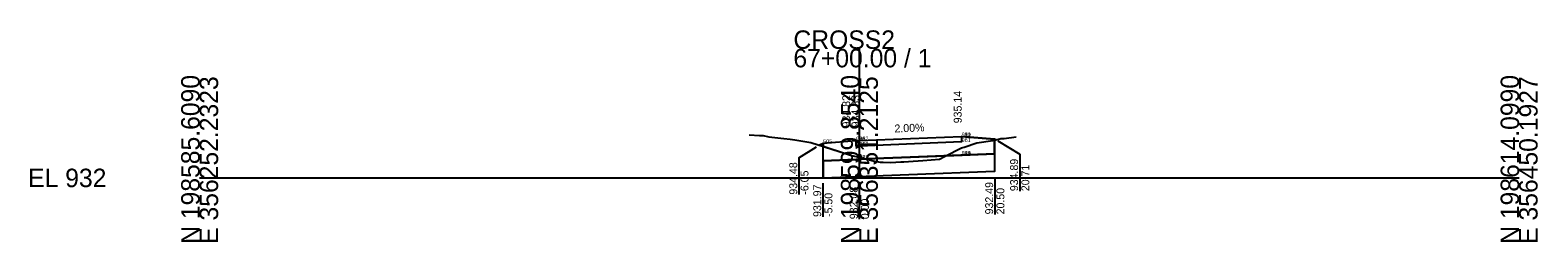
# Model space of a CAD drawing. Extents: x -26 to 203, y -10 to 14021.
# Drawn here: x -25.7 to 202.8, y 7990.3 to 8022.4 of the extents above; entities that cross this region are included whole.
import ezdxf

# ---------------------------------------------------------------- set-up
doc = ezdxf.new("R2010")
doc.units = 0
for name, color, linetype in [('Default', 7, 'Continuous'), ('P_E_XS_Ground', 7, 'Continuous'), ('P_XS', 7, 'Continuous'), ('P_XS_Bold', 7, 'Continuous'), ('P_XS_EAR_CommonGrnd', 7, 'Continuous'), ('P_XS_Lane', 7, 'Continuous'), ('P_XS_Rock', 7, 'Continuous')]:
    doc.layers.add(name, color=color, linetype=linetype)

msp = doc.modelspace()

# ---------------------------------------------------------------- linework, layer by layer
at = {"layer": 'Default'}
for p, q in [((100, 8000), (100, 8019.56)), ((0, 8000), (100, 8000)), ((100, 8000), (200, 8000))]:
    msp.add_line(p, q, dxfattribs=at)
at = {"layer": 'P_E_XS_Ground'}
for p, q in [((83.29, 8006.52), (84.86, 8006.43)), ((84.86, 8006.43), (85.44, 8006.41)), ((85.44, 8006.41), (86.29, 8006.24)), ((86.29, 8006.24), (88.57, 8005.98)), ((88.57, 8005.98), (89.52, 8005.86)), ((89.52, 8005.86), (90.2, 8005.76)), ((90.2, 8005.76), (92.65, 8005.38)), ((117.79, 8005.3), (120.21, 8005.69)), ((120.21, 8005.69), (120.94, 8005.82)), ((120.94, 8005.82), (121.46, 8005.97)), ((121.46, 8005.97), (121.93, 8005.97)), ((121.93, 8005.97), (123.74, 8006.21)), ((92.65, 8005.38), (97.89, 8003.7)), ((97.89, 8003.7), (98.8, 8003.42)), ((98.8, 8003.42), (99.51, 8003.26)), ((99.51, 8003.26), (100, 8003.13)), ((112.16, 8002.86), (112.9, 8003.25)), ((112.9, 8003.25), (115.47, 8004.57)), ((115.47, 8004.57), (115.86, 8004.68)), ((115.86, 8004.68), (117.79, 8005.3)), ((100, 8003.13), (102.1, 8002.61)), ((102.1, 8002.61), (103.13, 8002.4)), ((103.13, 8002.4), (103.59, 8002.39)), ((103.59, 8002.39), (104.79, 8002.34)), ((104.79, 8002.34), (106.28, 8002.43)), ((106.28, 8002.43), (106.76, 8002.43)), ((106.76, 8002.43), (107.45, 8002.48)), ((107.45, 8002.48), (109.62, 8002.63)), ((109.62, 8002.63), (112.16, 8002.86))]:
    msp.add_line(p, q, dxfattribs=at)
at = {"layer": 'P_XS'}
for p, q in [((99.5, 8005.64), (99.5, 8004.81)), ((115.5, 8006.28), (115.5, 8005.45)), ((120.5, 8003.65), (120.5, 8005.88)), ((94.5, 8002.61), (94.5, 8005.24)), ((99.5, 8004.81), (100, 8004.83)), ((115.5, 8005.45), (100, 8004.83)), ((120.5, 8003.65), (100, 8002.83)), ((120.5, 8003.65), (120.5, 8000.98)), ((99.5, 8002.81), (94.5, 8002.61)), ((94.5, 8002.61), (94.5, 7999.94)), ((120.5, 8000.98), (94.5, 7999.94)), ((99.5, 8002.81), (100, 8002.83))]:
    msp.add_line(p, q, dxfattribs=at)
at = {"layer": 'P_XS_EAR_CommonGrnd'}
for points in [[(94.5, 8004.79), (97.89, 8003.7), (98.8, 8003.42), (99.51, 8003.26), (100, 8003.13), (101.04, 8002.87), (113.11, 8003.35), (115.47, 8004.57), (115.86, 8004.68), (117.79, 8005.3), (120.21, 8005.69), (120.5, 8005.74), (120.5, 8005.88), (115.5, 8006.28), (115.5, 8005.45), (100, 8004.83), (99.5, 8004.81), (99.5, 8005.64), (94.5, 8005.24)], [(100, 8005.66), (115.5, 8006.28), (115.5, 8005.45), (100, 8004.83), (99.5, 8004.81), (99.5, 8005.64)], [(120.21, 8005.69), (120.5, 8005.74), (120.5, 8003.65), (113.11, 8003.35), (115.47, 8004.57), (115.86, 8004.68), (117.79, 8005.3)], [(120.5, 8005.74), (120.71, 8005.78), (120.5, 8005.88)], [(93.95, 8004.97), (94.5, 8004.79), (94.5, 8005.24)], [(94.5, 8004.79), (97.89, 8003.7), (98.8, 8003.42), (99.51, 8003.26), (100, 8003.13), (101.04, 8002.87), (100, 8002.83), (99.5, 8002.81), (94.5, 8002.61)], [(107.45, 8002.48), (109.62, 8002.63), (112.16, 8002.86), (112.9, 8003.25), (113.11, 8003.35), (120.5, 8003.65), (120.5, 8000.98), (94.5, 7999.94), (94.5, 8002.61), (99.5, 8002.81), (100, 8002.83), (101.04, 8002.87), (102.1, 8002.61), (103.13, 8002.4), (103.59, 8002.39), (104.79, 8002.34), (106.28, 8002.43), (106.76, 8002.43)], [(107.45, 8002.48), (109.62, 8002.63), (112.16, 8002.86), (112.9, 8003.25), (113.11, 8003.35), (101.04, 8002.87), (102.1, 8002.61), (103.13, 8002.4), (103.59, 8002.39), (104.79, 8002.34), (106.28, 8002.43), (106.76, 8002.43)]]:
    msp.add_lwpolyline(points, close=True, dxfattribs=at)
at = {"layer": 'P_XS_Lane'}
for p, q in [((99.5, 8005.64), (94.5, 8005.24)), ((99.5, 8005.64), (100, 8005.66)), ((100, 8005.66), (115.5, 8006.28)), ((115.5, 8006.28), (120.5, 8005.88)), ((120.5, 8005.88), (120.71, 8005.78)), ((94.5, 8005.24), (93.95, 8004.97))]:
    msp.add_line(p, q, dxfattribs=at)
at = {"layer": 'P_XS_Rock'}
for p, q in [((120.99, 8005.6), (124.3, 8003.58)), ((90.83, 8003.06), (93.49, 8004.69)), ((124.3, 8003.58), (124.3, 7997.99)), ((90.83, 8003.06), (90.83, 7997.46)), ((94.46, 7999.2), (94.46, 7994.08)), ((99.99, 7999.43), (99.99, 7993.74)), ((120.52, 8000.07), (120.52, 7994.47))]:
    msp.add_line(p, q, dxfattribs=at)

# ---------------------------------------------------------------- texts
at = {"layer": 'Default'}
for s, p in [('CROSS2', (90, 8019.56)), ('67+00.00 / 1', (90, 8016.76)), ('EL 932', (-26, 7998.6))]:
    msp.add_text(s, height=2.8, dxfattribs=at).set_placement(p)
for s, p in [('N 198585.6090', (0, 7990)), ('E 356252.2323', (2.8, 7990)), ('N 198599.8540', (100, 7990)), ('E 356351.2125', (102.8, 7990)), ('N 198614.0990', (200, 7990)), ('E 356450.1927', (202.8, 7990))]:
    msp.add_text(s, height=2.8, rotation=90, dxfattribs=at).set_placement(p)
at = {"layer": 'P_XS_Bold'}
for s, p in [('505', (94.5, 8005.24)), ('951', (99.5, 8005.64)), ('9', (99.5, 8005.64)), ('900', (99.5, 8005.64)), ('952', (100, 8005.66)), ('952', (100, 8005.66)), ('951', (115.5, 8006.28)), ('9', (115.5, 8006.28)), ('900', (115.5, 8006.28)), ('910', (115.5, 8006.28)), ('961', (115.5, 8005.45)), ('961', (99.5, 8004.81)), ('971', (99.5, 8002.81)), ('998', (99.5, 8002.81)), ('962', (100, 8004.83)), ('962', (100, 8004.83)), ('972', (100, 8002.83)), ('972', (100, 8002.83)), ('540', (115.5, 8003.45)), ('971', (115.5, 8003.45)), ('998', (115.5, 8003.45))]:
    msp.add_text(s, height=0.6, dxfattribs=at).set_placement(p)
at = {"layer": 'P_XS_Rock'}
for s, rotation, p in [('934.82', 90, (98.6, 8007.65)), ('934.83', 90, (100, 8007.66)), ('934.83', 90, (100, 8007.66)), ('934.83', 90, (100, 8007.66)), ('934.83', 90, (100, 8007.66)), ('935.14', 90, (115.5, 8008.28)), ('2.00%', 2.2906, (105.34, 8006.88)), ('934.48', 90, (90.58, 7997.46)), ('-6.05', 90, (92.28, 7997.46)), ('934.89', 90, (124.05, 7997.99)), ('20.71', 90, (125.75, 7997.99)), ('931.97', 90, (94.21, 7994.08)), ('932.49', 90, (120.27, 7994.47)), ('-5.50', 90, (95.91, 7994.08)), ('932.08', 90, (99.74, 7993.74)), ('0.00', 90, (101.44, 7993.74)), ('20.50', 90, (121.97, 7994.47))]:
    msp.add_text(s, height=1.2, rotation=rotation, dxfattribs=at).set_placement(p)

doc.saveas('drawing.dxf')
